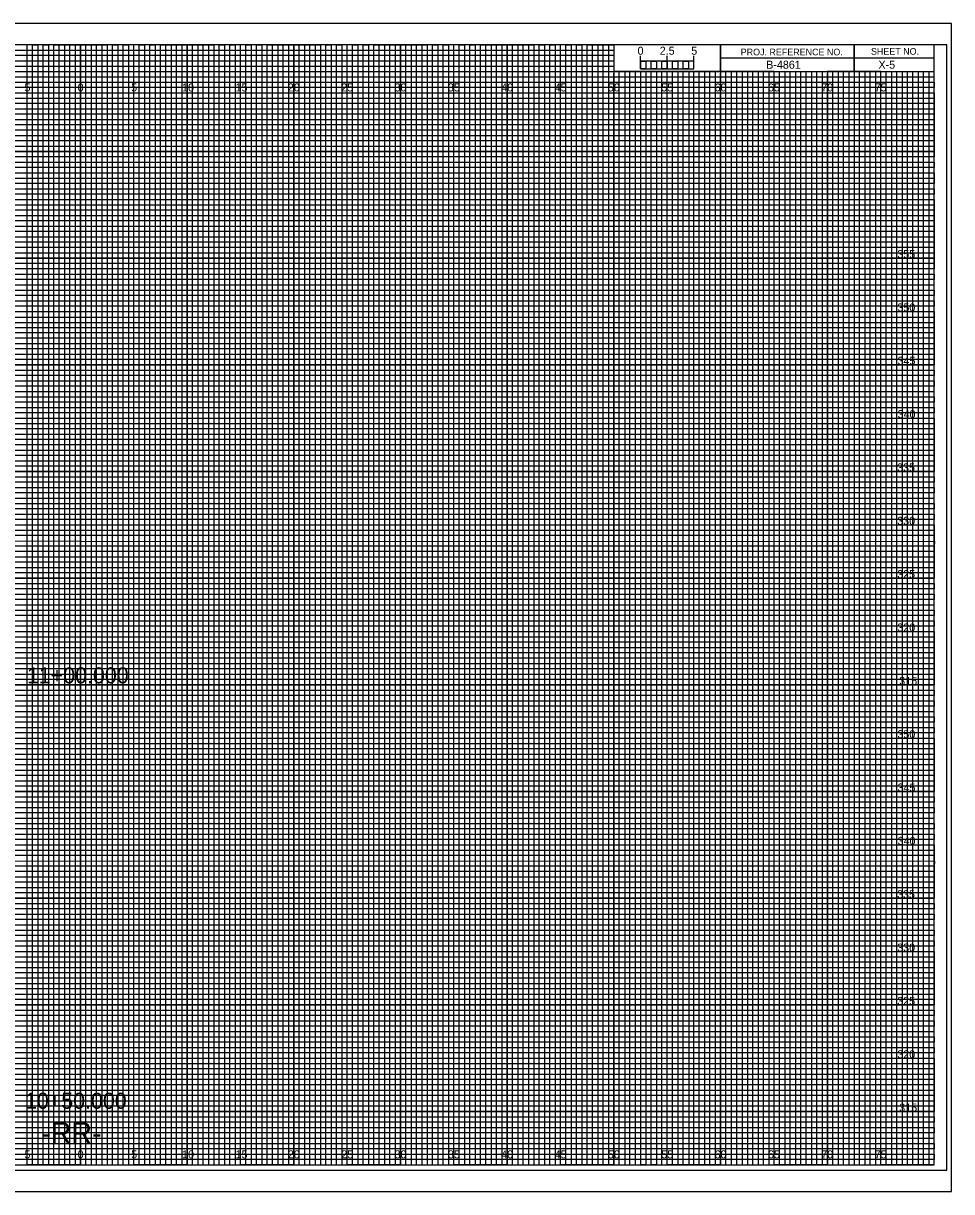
# Model space of a CAD drawing. Extents: x -7 to 162, y -2 to 327.
# Drawn here: x 74.6 to 161.7, y -2.5 to 107 of the extents above; entities that cross this region are included whole.
import ezdxf

# ---------------------------------------------------------------- set-up
doc = ezdxf.new("R2010")
doc.units = 0
for name, color, linetype in [('Exist Cross Section Cell', 7, 'Continuous'), ('Exist XS Center Line Elevation Label', 7, 'Continuous'), ('Exist XS Ground Line', 7, 'Continuous'), ('Old_Level_1', 7, 'Continuous'), ('Prop Retaining Wall', 7, 'Continuous'), ('Prop XS Bar Scale Labels', 7, 'Continuous'), ('Prop XS Bridge', 7, 'Continuous'), ('Prop XS Ditch Standard Text', 7, 'Continuous'), ('Prop XS EOT Tick Mark', 7, 'Continuous'), ('Prop XS Finish Grade Concrete', 7, 'Continuous'), ('Prop XS Finish Grade Earthwork', 7, 'Continuous'), ('Prop XS Label Text', 7, 'Continuous'), ('Prop XS SS Elevation Text', 7, 'Continuous'), ('Prop XS Subgrade', 7, 'Continuous'), ('Scratch_Level_3', 7, 'Continuous'), ('Scratch_Level_4', 7, 'Continuous'), ('Typical Arrow Superelevation CELL', 7, 'Continuous')]:
    doc.layers.add(name, color=color, linetype=linetype)

msp = doc.modelspace()

# ---------------------------------------------------------------- linework, layer by layer
at = {"layer": 'Exist XS Center Line Elevation Label'}
for points in [[(72.5, 0), (77.5, 0), (77.5, 105), (82.5, 105), (82.5, 0), (87.5, 0), (87.5, 105), (92.5, 105), (92.5, 0), (97.5, 0), (97.5, 105), (102.5, 105), (102.5, 0), (107.5, 0), (107.5, 105), (112.5, 105), (112.5, 0), (117.5, 0), (117.5, 105), (122.5, 105), (122.5, 0), (127.5, 0), (127.5, 105), (129.97, 105), (130, 105), (130, 102.5), (132.5, 102.5), (132.5, 0), (137.5, 0), (137.5, 102.5), (142.5, 102.5), (142.5, 0), (147.5, 0), (147.5, 102.5), (152.5, 102.5), (152.5, 0), (157.5, 0), (157.5, 102.5)], [(0, 102.5), (137.5, 102.5)], [(0, 92.5), (160, 92.5), (160, 97.5), (0, 97.5)], [(0, 82.5), (160, 82.5), (160, 87.5), (0, 87.5)], [(0, 72.5), (160, 72.5), (160, 77.5), (0, 77.5)], [(0, 62.5), (160, 62.5), (160, 67.5), (0, 67.5)], [(0, 52.5), (160, 52.5), (160, 57.5), (0, 57.5)], [(0, 42.5), (160, 42.5), (160, 47.5), (0, 47.5)], [(0, 32.5), (160, 32.5), (160, 37.5), (0, 37.5)], [(0, 22.5), (160, 22.5), (160, 27.5), (0, 27.5)], [(0, 12.5), (160, 12.5), (160, 17.5), (0, 17.5)], [(0, 2.5), (160, 2.5), (160, 7.5), (0, 7.5)]]:
    msp.add_lwpolyline(points, dxfattribs=at)
at = {"layer": 'Exist XS Ground Line'}
for p, q in [((75, 105), (70, 105)), ((75, 0), (75, 105)), ((85, 105), (80, 105)), ((80, 105), (80, 0)), ((85, 0), (85, 105)), ((95, 105), (90, 105)), ((90, 105), (90, 0)), ((95, 0), (95, 105)), ((105, 105), (100, 105)), ((100, 105), (100, 0)), ((105, 0), (105, 105)), ((115, 105), (110, 105)), ((110, 105), (110, 0)), ((115, 0), (115, 105)), ((125, 105), (120, 105)), ((120, 105), (120, 0)), ((125, 0), (125, 105)), ((130, 105), (130, 0)), ((135, 0), (135, 102.5)), ((145, 102.5), (140, 102.5)), ((140, 102.5), (140, 0)), ((145, 0), (145, 102.5)), ((155, 102.5), (150, 102.5)), ((150, 102.5), (150, 0)), ((155, 0), (155, 102.5)), ((80, 0), (75, 0)), ((90, 0), (85, 0)), ((100, 0), (95, 0)), ((110, 0), (105, 0)), ((120, 0), (115, 0)), ((130, 0), (125, 0)), ((140, 0), (135, 0)), ((150, 0), (145, 0)), ((160, 0), (155, 0)), ((160, 0), (160, 0))]:
    msp.add_line(p, q, dxfattribs=at)
for points in [[(0, 100), (160, 100), (160, 95), (0, 95)], [(0, 90), (160, 90), (160, 85), (0, 85)], [(0, 80), (160, 80), (160, 75), (0, 75)], [(0, 70), (160, 70), (160, 65), (0, 65)], [(0, 60), (160, 60), (160, 55), (0, 55)], [(0, 50), (160, 50), (160, 45), (0, 45)], [(0, 40), (160, 40), (160, 35), (0, 35)], [(0, 30), (160, 30), (160, 25), (0, 25)], [(0, 20), (160, 20), (160, 15), (0, 15)], [(0, 10), (160, 10), (160, 5), (0, 5)]]:
    msp.add_lwpolyline(points, dxfattribs=at)
at = {"layer": 'Old_Level_1'}
msp.add_lwpolyline([(-5.4, -0.5), (161.2, -0.5), (161.2, 105), (-5.4, 105)], close=True, dxfattribs=at)
at = {"layer": 'Prop XS Bridge'}
for p, q in [((75, 0), (75, 105)), ((80, 0), (80, 105)), ((85, 0), (85, 105)), ((90, 0), (90, 105)), ((95, 0), (95, 105)), ((100, 0), (100, 105)), ((105, 0), (105, 105)), ((110, 0), (110, 105)), ((115, 0), (115, 105)), ((120, 0), (120, 105)), ((125, 0), (125, 105)), ((130, 0), (130, 102.34)), ((135, 0), (135, 102.34)), ((140, 0), (140, 102.34)), ((145, 0), (145, 102.34)), ((150, 0), (150, 102.34)), ((155, 0), (155, 102.34)), ((0, 100), (160, 100)), ((0, 95), (160, 95)), ((0, 90), (160, 90)), ((0, 85), (160, 85)), ((0, 80), (160, 80)), ((0, 75), (160, 75)), ((0, 70), (160, 70)), ((0, 65), (160, 65)), ((0, 60), (160, 60)), ((0, 55), (160, 55)), ((0, 50), (160, 50)), ((0, 45), (160, 45)), ((0, 40), (160, 40)), ((0, 35), (160, 35)), ((0, 30), (160, 30)), ((0, 25), (160, 25)), ((0, 20), (160, 20)), ((0, 15), (160, 15)), ((0, 10), (160, 10)), ((0, 5), (160, 5))]:
    msp.add_line(p, q, dxfattribs=at)
at = {"layer": 'Prop XS EOT Tick Mark'}
for p, q in [((152.5, 105), (152.5, 102.5)), ((152.5, 102.5), (152.5, 105)), ((160, 103.75), (140, 103.75)), ((140, 103.75), (140, 102.5)), ((140, 102.5), (160, 102.5))]:
    msp.add_line(p, q, dxfattribs=at)
for points in [[(160, 105), (0, 105), (0, 0), (160, 0)], [(140, 105), (130, 105), (130, 102.52), (140, 102.52)], [(160, 105), (140, 105), (140, 102.5), (160, 102.5)]]:
    msp.add_lwpolyline(points, close=True, dxfattribs=at)
at = {"layer": 'Prop XS Finish Grade Earthwork'}
for p, q in [((161.65, 107), (-6.7, 107)), ((-6.7, -2.5), (161.65, -2.5))]:
    msp.add_line(p, q, dxfattribs=at)
at = {"layer": 'Prop XS Label Text'}
for p, q in [((133.5, 102.5), (133, 102.5)), ((133, 102.5), (133, 0)), ((133.5, 0), (133.5, 102.5)), ((134.5, 102.5), (134, 102.5)), ((134, 102.5), (134, 0)), ((134.5, 0), (134.5, 102.5)), ((133, 0), (132.5, 0)), ((134, 0), (133.5, 0))]:
    msp.add_line(p, q, dxfattribs=at)
for points in [[(75, 0), (75.5, 0), (75.5, 105), (76, 105), (76, 0)], [(76, 0), (76.5, 0), (76.5, 105), (77, 105), (77, 0)], [(77.5, 0), (78, 0), (78, 105), (78.5, 105), (78.5, 0)], [(78.5, 0), (79, 0), (79, 105), (79.5, 105), (79.5, 0)], [(80, 0), (80.5, 0), (80.5, 105), (81, 105), (81, 0)], [(81, 0), (81.5, 0), (81.5, 105), (82, 105), (82, 0)], [(82.5, 0), (83, 0), (83, 105), (83.5, 105), (83.5, 0)], [(83.5, 0), (84, 0), (84, 105), (84.5, 105), (84.5, 0)], [(85, 0), (85.5, 0), (85.5, 105), (86, 105), (86, 0)], [(86, 0), (86.5, 0), (86.5, 105), (87, 105), (87, 0)], [(87.5, 0), (88, 0), (88, 105), (88.5, 105), (88.5, 0)], [(88.5, 0), (89, 0), (89, 105), (89.5, 105), (89.5, 0)], [(90, 0), (90.5, 0), (90.5, 105), (91, 105), (91, 0)], [(91, 0), (91.5, 0), (91.5, 105), (92, 105), (92, 0)], [(92.5, 0), (93, 0), (93, 105), (93.5, 105), (93.5, 0)], [(93.5, 0), (94, 0), (94, 105), (94.5, 105), (94.5, 0)], [(95, 0), (95.5, 0), (95.5, 105), (96, 105), (96, 0)], [(96, 0), (96.5, 0), (96.5, 105), (97, 105), (97, 0)], [(97.5, 0), (98, 0), (98, 105), (98.5, 105), (98.5, 0)], [(98.5, 0), (99, 0), (99, 105), (99.5, 105), (99.5, 0)], [(100, 0), (100.5, 0), (100.5, 105), (101, 105), (101, 0)], [(101, 0), (101.5, 0), (101.5, 105), (102, 105), (102, 0)], [(102.5, 0), (103, 0), (103, 105), (103.5, 105), (103.5, 0)], [(103.5, 0), (104, 0), (104, 105), (104.5, 105), (104.5, 0)], [(105, 0), (105.5, 0), (105.5, 105), (106, 105), (106, 0)], [(106, 0), (106.5, 0), (106.5, 105), (107, 105), (107, 0)], [(107.5, 0), (108, 0), (108, 105), (108.5, 105), (108.5, 0)], [(108.5, 0), (109, 0), (109, 105), (109.5, 105), (109.5, 0)], [(110, 0), (110.5, 0), (110.5, 105), (111, 105), (111, 0)], [(111, 0), (111.5, 0), (111.5, 105), (112, 105), (112, 0)], [(112.5, 0), (113, 0), (113, 105), (113.5, 105), (113.5, 0)], [(113.5, 0), (114, 0), (114, 105), (114.5, 105), (114.5, 0)], [(115, 0), (115.5, 0), (115.5, 105), (116, 105), (116, 0)], [(116, 0), (116.5, 0), (116.5, 105), (117, 105), (117, 0)], [(117.5, 0), (118, 0), (118, 105), (118.5, 105), (118.5, 0)], [(118.5, 0), (119, 0), (119, 105), (119.5, 105), (119.5, 0)], [(120, 0), (120.5, 0), (120.5, 105), (121, 105), (121, 0)], [(121, 0), (121.5, 0), (121.5, 105), (122, 105), (122, 0)], [(122.5, 0), (123, 0), (123, 105), (123.5, 105), (123.5, 0)], [(123.5, 0), (124, 0), (124, 105), (124.5, 105), (124.5, 0)], [(125, 0), (125.5, 0), (125.5, 105), (126, 105), (126, 0)], [(126, 0), (126.5, 0), (126.5, 105), (127, 105), (127, 0)], [(127.5, 0), (128, 0), (128, 105), (128.5, 105), (128.5, 0)], [(128.5, 0), (129, 0), (129, 105), (129.5, 105), (129.5, 0)], [(130, 0), (130.5, 0), (130.5, 102.5), (131.01, 102.5), (131.01, 0)], [(131, 0), (131.5, 0), (131.5, 102.5), (132, 102.5), (132, 0)], [(135, 0), (135.49, 0), (135.49, 102.5), (136, 102.5), (136, 0)], [(136, 0), (136.5, 0), (136.5, 102.5), (137.03, 102.5), (137.03, 0)], [(137.5, 0), (138, 0), (138, 102.5), (138.5, 102.5), (138.5, 0)], [(138.5, 0), (139, 0), (139, 102.5), (139.5, 102.5), (139.5, 0)], [(140, 0), (140.5, 0), (140.5, 102.5), (141, 102.5), (141, 0)], [(141, 0), (141.5, 0), (141.5, 102.5), (142, 102.5), (142, 0)], [(142.5, 0), (143, 0), (143, 102.5), (143.5, 102.5), (143.5, 0)], [(143.5, 0), (144, 0), (144, 102.5), (144.5, 102.5), (144.5, 0)], [(145, 0), (145.5, 0), (145.5, 102.5), (146, 102.5), (146, 0)], [(146, 0), (146.5, 0), (146.5, 102.5), (147, 102.5), (147, 0)], [(147.5, 0), (148, 0), (148, 102.5), (148.5, 102.5), (148.5, 0)], [(148.5, 0), (149, 0), (149, 102.5), (149.5, 102.5), (149.5, 0)], [(150, 0), (150.5, 0), (150.5, 102.5), (151, 102.5), (151, 0)], [(151, 0), (151.5, 0), (151.5, 102.5), (152, 102.5), (152, 0)], [(152.5, 0), (153, 0), (153, 102.5), (153.5, 102.5), (153.5, 0)], [(153.5, 0), (154, 0), (154, 102.5), (154.5, 102.5), (154.5, 0)], [(155, 0), (155.5, 0), (155.5, 102.5), (156, 102.5), (156, 0)], [(156, 0), (156.5, 0), (156.5, 102.5), (157, 102.5), (157, 0)], [(157.5, 0), (158, 0), (158, 102.5), (158.5, 102.5), (158.5, 0)], [(158.5, 0), (159, 0), (159, 102.5), (159.5, 102.5), (159.5, 0)]]:
    msp.add_lwpolyline(points, dxfattribs=at)
at = {"layer": 'Prop XS Subgrade'}
msp.add_lwpolyline([(-6.7, -2.5), (161.65, -2.5), (161.65, 107), (-6.7, 107)], close=True, dxfattribs=at)
at = {"layer": 'Scratch_Level_3'}
for p, q in [((0, 104.5), (130, 104.5)), ((130, 104.5), (130, 103.99)), ((130, 103.99), (0, 103.99)), ((0, 103.5), (130, 103.5)), ((130, 102.95), (0, 102.95)), ((130, 103.5), (130, 102.95)), ((0, 102), (160, 102))]:
    msp.add_line(p, q, dxfattribs=at)
for points in [[(0, 101.5), (135, 101.5), (160, 101.5), (160, 101), (0, 101)], [(0, 100.5), (160, 100.5), (160, 99.5), (0, 99.5)], [(0, 99), (160, 99), (160, 98.5), (0, 98.49)], [(0, 98), (160, 98), (160, 97), (0, 97)], [(0, 96.5), (160, 96.5), (160, 96), (0, 96)], [(0, 95.5), (160, 95.5), (160, 94.5), (0, 94.5)], [(0, 94), (160, 94), (160, 93.5), (0, 93.5)], [(0, 93), (160, 93), (160, 92), (0, 92)], [(0, 91.5), (160, 91.5), (160, 91), (0, 91)], [(0, 90.5), (160, 90.5), (160, 89.5), (0, 89.5)], [(0, 89), (160, 89), (160, 88.5), (0, 88.5)], [(0, 88), (160, 88), (160, 86.98), (160, 86.5), (160, 86), (0, 86)], [(0, 87), (160, 87), (160, 86.5), (0, 86.5)], [(0, 85.5), (160, 85.5), (160, 84.5), (0, 84.52)], [(0, 84.52), (160, 84.5), (160, 84), (0, 84)], [(0, 83.5), (160, 83.5), (160, 83), (0, 83)], [(0, 82), (160, 82), (160, 81.5), (0, 81.5)], [(0, 81), (160, 81), (160, 80.5), (0, 80.5)], [(-0.04, 79.45), (160, 79.45), (160, 78.94), (-0.04, 78.94)], [(0, 78.5), (160, 78.5), (160, 78), (0, 78)], [(0, 77), (160, 77), (160, 76.5), (0, 76.5)], [(0, 76), (160, 76), (160, 75.5), (0, 75.5)], [(0, 74.5), (160, 74.5), (160, 74), (0, 74)], [(0, 73.5), (160, 73.5), (160, 73), (0, 73)], [(0, 72), (160, 72), (160, 71.5), (0, 71.5)], [(0, 71), (160, 71), (160, 70.5), (0, 70.5)], [(0, 69.5), (160, 69.5), (160, 68.99), (0, 69)], [(0, 68.5), (160, 68.5), (160, 68), (0, 68)], [(0, 67), (160, 67), (160, 66.5), (0, 66.5)], [(0, 66), (160, 66), (160, 65.5), (0, 65.5)], [(0, 64.5), (160, 64.5), (160, 64), (0, 64)], [(0, 63.5), (160, 63.5), (160, 63), (0, 63)], [(0, 62), (160, 62), (160, 61.5), (0, 61.5)], [(0, 61), (160, 61), (160, 60.5), (0, 60.5)], [(0, 59.5), (160, 59.5), (160, 59), (0, 59)], [(0, 58.5), (160.03, 58.45), (160, 58), (0, 58)], [(0, 57), (160, 57), (160, 56.5), (0, 56.5)], [(0, 56), (160, 56), (160, 55.5), (0, 55.5)], [(0, 54.5), (160, 54.5), (160, 54), (0, 54)], [(0, 53.5), (160, 53.5), (160, 53), (0, 53)], [(0, 52), (160, 52), (160, 51.5), (0, 51.5)], [(0, 51), (160, 51), (160, 50.5), (0, 50.5)], [(0, 49.5), (160, 49.5), (160, 49), (0, 49)], [(0, 48.5), (160, 48.5), (160, 48), (0, 48)], [(0, 47), (160, 47), (160, 46.5), (0, 46.5)], [(0, 46), (160, 46), (160, 45.5), (0, 45.5)], [(0, 44.5), (160, 44.5), (160, 44), (0, 44)], [(0, 43.5), (160, 43.5), (160, 43), (0, 43)], [(0, 42), (160, 42), (160, 41.5), (0, 41.5)], [(0, 41), (160, 41), (160, 40.5), (0, 40.5)], [(0, 39.5), (160, 39.5), (160, 38.99), (0, 39)], [(0, 38.5), (160, 38.5), (160, 38), (0, 38)], [(0, 37), (160, 37), (160, 36.5), (0, 36.5)], [(0, 36), (160, 36), (160, 35.5), (0, 35.5)], [(0, 34.5), (160, 34.5), (160, 34), (0, 34)], [(0, 33.5), (160, 33.5), (160, 33), (0, 33)], [(0, 32), (160, 32), (160, 31.5), (0, 31.5)], [(0, 31), (160, 31), (160, 30.5), (0, 30.5)], [(0, 29.5), (160, 29.5), (160, 29), (0, 29)], [(0, 28.5), (160.03, 28.46), (160, 28), (0, 28)], [(0, 27), (160, 27), (160, 26.5), (0, 26.5)], [(0, 26), (160, 26), (160, 25.5), (0, 25.5)], [(0, 24.5), (160, 24.5), (160, 24), (0, 24)], [(0, 23.5), (160, 23.5), (160, 23), (0, 23)], [(0, 22), (160, 22), (160, 21.5), (0, 21.5)], [(0, 21), (160, 21), (160, 20.5), (0, 20.5)], [(0, 19.5), (160, 19.5), (160, 19), (0, 19)], [(0, 18.5), (160, 18.5), (160, 18), (0, 18)], [(0, 17), (160, 17), (160, 16.5), (0, 16.5)], [(0, 16), (160, 16), (160, 15.5), (0, 15.5)], [(0, 14.5), (160, 14.5), (160, 14), (0, 14)], [(0, 13.5), (160, 13.5), (160, 13), (0, 13)], [(0, 12), (160, 12), (160, 11.5), (0, 11.5)], [(0, 11), (160, 11), (160, 10.5), (0, 10.5)], [(0, 9.5), (160, 9.5), (160, 9), (0, 9)], [(0, 8.5), (160, 8.5), (160, 8), (0, 8)], [(0, 7), (160, 7), (160, 6.5), (0, 6.5)], [(0, 6), (160, 6), (160, 5.5), (0, 5.5)], [(0, 4.5), (160, 4.5), (160, 4), (0, 4)], [(0, 3.5), (160, 3.5), (160, 3), (0, 3)], [(0, 2), (160, 2), (160, 1.5), (0, 1.5)], [(0, 1), (160, 1), (160, 0.5), (0, 0.5)]]:
    msp.add_lwpolyline(points, dxfattribs=at)
at = {"layer": 'Scratch_Level_4'}
for p, q in [((132.5, 102.75), (132.5, 103.95)), ((132.5, 103.45), (132.5, 103.95)), ((135, 102.75), (135, 103.95)), ((137.5, 102.75), (137.5, 103.95)), ((137.5, 103.45), (137.5, 103.95))]:
    msp.add_line(p, q, dxfattribs=at)
for points in [[(137.5, 103.45), (132.5, 103.45), (132.5, 102.75), (137.5, 102.75)], [(132.5, 103.45), (133, 103.45), (133, 102.75), (132.5, 102.75)], [(133.5, 103.45), (134, 103.45), (134, 102.75), (133.5, 102.75)], [(134.5, 103.45), (135, 103.45), (135, 102.75), (134.5, 102.75)], [(135.5, 103.45), (136, 103.45), (136, 102.75), (135.5, 102.75)], [(136.5, 103.45), (137, 103.45), (137, 102.75), (136.5, 102.75)]]:
    msp.add_lwpolyline(points, close=True, dxfattribs=at)

# ---------------------------------------------------------------- texts
at = {"layer": 'Exist Cross Section Cell'}
for s, p in [('5', (74.74, 100.62)), ('0', (79.73, 100.62)), ('0', (79.73, 100.62)), ('5', (84.74, 100.62)), ('10', (89.52, 100.62)), ('15', (94.53, 100.62)), ('20', (99.43, 100.62)), ('25', (104.44, 100.62)), ('30', (109.43, 100.62)), ('35', (114.44, 100.62)), ('40', (119.43, 100.62)), ('45', (124.44, 100.62)), ('50', (129.43, 100.62)), ('55', (134.44, 100.62)), ('60', (139.43, 100.62)), ('65', (144.44, 100.62)), ('70', (149.43, 100.62)), ('75', (154.44, 100.62)), ('5', (74.74, 0.62)), ('0', (79.73, 0.62)), ('0', (79.73, 0.62)), ('5', (84.74, 0.62)), ('10', (89.52, 0.62)), ('15', (94.53, 0.62)), ('20', (99.43, 0.62)), ('25', (104.44, 0.62)), ('30', (109.43, 0.62)), ('35', (114.44, 0.62)), ('40', (119.43, 0.62)), ('45', (124.44, 0.62)), ('50', (129.43, 0.62)), ('55', (134.44, 0.62)), ('60', (139.43, 0.62)), ('65', (144.44, 0.62)), ('70', (149.43, 0.62)), ('75', (154.44, 0.62))]:
    msp.add_text(s, height=0.75, dxfattribs=at).set_placement(p)
at = {"layer": 'Prop Retaining Wall'}
msp.add_text('-RR-', height=2, dxfattribs=at).set_placement((76.32, 2))
at = {"layer": 'Prop XS Bar Scale Labels'}
for s, p in [('2.5', (134.29, 104.06)), ('5', (137.24, 104.06))]:
    msp.add_text(s, height=0.75, dxfattribs=at).set_placement(p)
at = {"layer": 'Prop XS Ditch Standard Text'}
for s, p in [('355', (156.56, 85)), ('350', (156.57, 80)), ('345', (156.58, 75)), ('340', (156.59, 70)), ('335', (156.54, 65)), ('330', (156.55, 60)), ('325', (156.55, 55)), ('320', (156.56, 50)), ('315', (156.74, 45)), ('350', (156.57, 40)), ('345', (156.58, 35)), ('340', (156.59, 30)), ('335', (156.54, 25)), ('330', (156.55, 20)), ('325', (156.55, 15)), ('320', (156.56, 10)), ('315', (156.74, 5))]:
    msp.add_text(s, height=0.75, dxfattribs=at).set_placement(p)
at = {"layer": 'Prop XS EOT Tick Mark'}
for s, p in [('PROJ. REFERENCE NO.', (141.88, 104)), ('SHEET NO.', (154.09, 104.06))]:
    msp.add_text(s, height=0.625, dxfattribs=at).set_placement(p)
at = {"layer": 'Prop XS Finish Grade Concrete'}
for s, p in [('11+00.000', (74.97, 45.14)), ('10+50.000', (74.79, 5.27))]:
    msp.add_text(s, height=1.5, dxfattribs=at).set_placement(p)
at = {"layer": 'Prop XS SS Elevation Text'}
msp.add_text('B-4861', height=0.75, dxfattribs=at).set_placement((144.27, 102.75))
at = {"layer": 'Scratch_Level_4'}
msp.add_text('0', height=0.75, dxfattribs=at).set_placement((132.21, 104.06))
at = {"layer": 'Typical Arrow Superelevation CELL'}
msp.add_text('X-5', height=0.75, dxfattribs=at).set_placement((154.79, 102.75))

doc.saveas('drawing.dxf')
